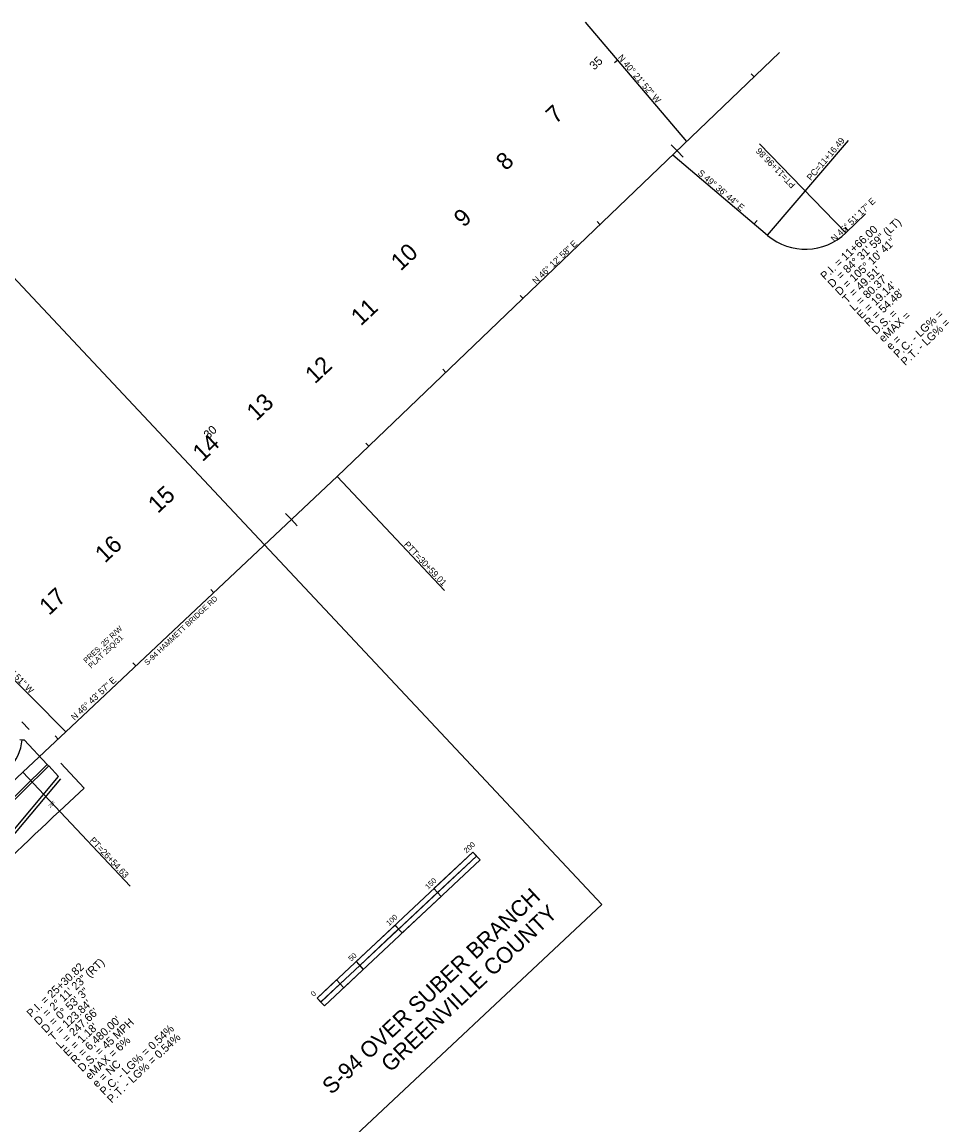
# Model space of a CAD drawing. Extents: x 1623239 to 1625698, y 1118659 to 1120751.
# Drawn here: x 1624829 to 1625698, y 1119717 to 1120751 of the extents above; entities that cross this region are included whole.
import ezdxf

# ---------------------------------------------------------------- set-up
doc = ezdxf.new("R2010")
doc.units = 0
for name, color, linetype in [('RD_EX_DV_TX_Prop', 7, 'Continuous'), ('RD_EX_Road Text', 7, 'Continuous'), ('RD_EX_RW_TX', 7, 'Continuous'), ('RD_HC_Cl', 7, 'Continuous'), ('RD_HC_CL_Rel', 7, 'Continuous'), ('RD_HC_Data', 7, 'Continuous'), ('RD_HC_Data_Tic', 7, 'Continuous'), ('RD_HC_TX_Sta50', 7, 'Continuous'), ('RD_PD_BOC', 7, 'Continuous'), ('RD_PD_CstnLmt', 7, 'Continuous'), ('RD_PD_CstnLmt_TX', 7, 'Continuous'), ('RD_PD_DR_ErosCtrl', 7, 'Continuous'), ('RD_PD_Final_TrvlWay', 7, 'Continuous'), ('RD_PD_PaveShd', 7, 'Continuous'), ('RD_PD_RW', 7, 'Continuous'), ('RD_SHT_ShtClip', 7, 'Continuous'), ('RD_SHT_TX', 7, 'Continuous')]:
    doc.layers.add(name, color=color, linetype=linetype)

msp = doc.modelspace()

# ---------------------------------------------------------------- linework, layer by layer
at = {"layer": 'RD_HC_Cl'}
for p, q in [((1625452.3, 1120638.9), (1625357.3, 1120750.8)), ((1625124.7, 1120324.9), (1625539.1, 1120722.2)), ((1625439.2, 1120626.4), (1625527.9, 1120550.9)), ((1625601.2, 1120553.3), (1625619.5, 1120571.1)), ((1624870.5, 1120085.7), (1625124.7, 1120324.9)), ((1624870.5, 1120085.7), (1624760.8, 1120196.1)), ((1624830.2, 1120047.8), (1624870.5, 1120085.7))]:
    msp.add_line(p, q, dxfattribs=at)
msp.add_arc((1625563.2, 1120592.4), 54.5, 229.6121, 314.1453, dxfattribs=at)
at = {"layer": 'RD_HC_CL_Rel'}
msp.add_arc((1629271.6, 1115329.3), 6480, 133.26746, 135.45725, dxfattribs=at)
at = {"layer": 'RD_HC_Data'}
for p, q in [((1625527.9, 1120550.9), (1625603.6, 1120639.8)), ((1625601.2, 1120553.3), (1625520.4, 1120636.5)), ((1625124.7, 1120324.9), (1625225.2, 1120218.2)), ((1624830.2, 1120047.8), (1624930.7, 1119941))]:
    msp.add_line(p, q, dxfattribs=at)
at = {"layer": 'RD_HC_Data_Tic'}
for p, q in [((1625387.5, 1120715.1), (1625384.5, 1120712.5)), ((1625515.2, 1120699.3), (1625512.5, 1120702.2)), ((1625443, 1120630.1), (1625437.5, 1120635.8)), ((1625448.6, 1120624.3), (1625443, 1120630.1)), ((1625370.8, 1120560.9), (1625368.1, 1120563.8)), ((1625515.4, 1120561.6), (1625518, 1120564.7)), ((1625603.4, 1120555.5), (1625600.6, 1120558.4)), ((1625298.7, 1120491.7), (1625295.9, 1120494.6)), ((1625226.5, 1120422.5), (1625223.7, 1120425.4)), ((1625154.3, 1120353.3), (1625151.5, 1120356.2)), ((1625081.7, 1120284.5), (1625076.2, 1120290.3)), ((1625087.2, 1120278.7), (1625081.7, 1120284.5)), ((1625008.9, 1120215.9), (1625006.1, 1120218.9)), ((1624936.1, 1120147.4), (1624933.3, 1120150.3)), ((1624863.2, 1120078.9), (1624860.5, 1120081.8))]:
    msp.add_line(p, q, dxfattribs=at)
at = {"layer": 'RD_PD_BOC'}
msp.add_line((1624827.4, 1120078.3), (1624829.4, 1120078.2), dxfattribs=at)
at = {"layer": 'RD_PD_CstnLmt'}
for p, q in [((1624863.6, 1120043.8), (1624854.4, 1120053.7)), ((1624814.5, 1119985.2), (1624863.6, 1120043.8))]:
    msp.add_line(p, q, dxfattribs=at)
at = {"layer": 'RD_PD_DR_ErosCtrl'}
msp.add_line((1624816.7, 1119983.1), (1624865.7, 1120041.6), dxfattribs=at)
at = {"layer": 'RD_PD_Final_TrvlWay'}
for p, q in [((1624829.4, 1120078.2), (1624831.4, 1120078)), ((1624831.4, 1120078), (1624853, 1120055.1)), ((1624781.7, 1119985), (1624853, 1120055.1))]:
    msp.add_line(p, q, dxfattribs=at)
msp.add_arc((1624789.5, 1120080.8), 40, 313.3287, 356.1548, dxfattribs=at)
at = {"layer": 'RD_PD_PaveShd'}
for p, q in [((1624783.1, 1119983.5), (1624854.4, 1120053.7)), ((1624853, 1120055.1), (1624854.3, 1120053.7))]:
    msp.add_line(p, q, dxfattribs=at)
at = {"layer": 'RD_PD_RW'}
for p, q in [((1624829.2, 1120094.9), (1624836, 1120087.7)), ((1624865.6, 1120056.3), (1624887.5, 1120033)), ((1624864.5, 1120011.4), (1624887.5, 1120033))]:
    msp.add_line(p, q, dxfattribs=at)
msp.add_arc((1629271.6, 1115329.3), 6430, 133.26746, 135.52479, dxfattribs=at)
at = {"layer": 'RD_SHT_ShtClip'}
for p, q in [((1624620.1, 1120726.2), (1625372.5, 1119923.9)), ((1625372.5, 1119923.9), (1624059.6, 1118692.6))]:
    msp.add_line(p, q, dxfattribs=at)
at = {"layer": 'RD_SHT_TX'}
for p, q in [((1625105.8, 1119836.1), (1625251.7, 1119972.9)), ((1625145.7, 1119866.6), (1625255.1, 1119969.2)), ((1625251.7, 1119972.9), (1625258.5, 1119965.6)), ((1625255.8, 1119968.5), (1625255.8, 1119968.5)), ((1625256.4, 1119967.8), (1625256.4, 1119967.8)), ((1625257.1, 1119967), (1625257.1, 1119967)), ((1625112.7, 1119828.8), (1625258.5, 1119965.6)), ((1625257.8, 1119966.3), (1625257.8, 1119966.3)), ((1625215.2, 1119938.7), (1625222, 1119931.4)), ((1625222, 1119931.4), (1625222, 1119931.4)), ((1625178.7, 1119904.5), (1625185.6, 1119897.2)), ((1625109.2, 1119832.5), (1625145.7, 1119866.6)), ((1625142.3, 1119870.3), (1625149.1, 1119863)), ((1625124, 1119853.2), (1625130.9, 1119845.9)), ((1625149.1, 1119863), (1625149.1, 1119863)), ((1625105.8, 1119836.1), (1625112.7, 1119828.8))]:
    msp.add_line(p, q, dxfattribs=at)
for points in [[(1625215.2, 1119938.7), (1625251.7, 1119972.9), (1625255.1, 1119969.2), (1625218.6, 1119935)], [(1625182.2, 1119900.8), (1625218.6, 1119935), (1625222, 1119931.4), (1625185.6, 1119897.2)], [(1625142.3, 1119870.3), (1625178.8, 1119904.5), (1625182.2, 1119900.9), (1625145.7, 1119866.6)], [(1625127.5, 1119849.6), (1625145.7, 1119866.6), (1625149.1, 1119863), (1625130.9, 1119845.9)], [(1625105.8, 1119836.1), (1625124, 1119853.2), (1625127.5, 1119849.5), (1625109.3, 1119832.4)]]:
    msp.add_lwpolyline(points, close=True, dxfattribs=at)

# ---------------------------------------------------------------- texts
at = {"layer": 'RD_EX_DV_TX_Prop'}
for s, p in [('7', (1625329.3, 1120654.6)), ('8', (1625282.6, 1120610.8)), ('9', (1625243.1, 1120557.7)), ('10', (1625184.1, 1120516.9)), ('11', (1625146.7, 1120465.4)), ('12', (1625103.8, 1120411.1)), ('13', (1625049, 1120376.3)), ('14', (1624998.4, 1120338.1)), ('15', (1624956.6, 1120289.7)), ('16', (1624907, 1120243.2)), ('17', (1624854.7, 1120194.1))]:
    msp.add_text(s, height=16, rotation=43.1627, dxfattribs=at).set_placement(p)
at = {"layer": 'RD_EX_Road Text'}
msp.add_text('S-94 HAMMETT BRIDGE RD', height=5, rotation=43.1627, dxfattribs=at).set_placement((1624946.7, 1120147.7))
at = {"layer": 'RD_EX_RW_TX'}
for s, p in [("PRES. 25' R/W", (1624889.6, 1120149.6)), ('PLAT 25Q/31', (1624894.2, 1120144.7))]:
    msp.add_text(s, height=5, rotation=43.2538, dxfattribs=at).set_placement(p)
at = {"layer": 'RD_HC_Data'}
for s, height, rotation, p in [('N 40%%d 21\' 52" W', 6, 310.3644, (1625387.1, 1120717.2)), ('PC=11+16.49', 6, 49.6121, (1625568.5, 1120601.7)), ('PT=11+96.86', 6, 134.1453, (1625554.5, 1120598.6)), ('S 49%%d 36\' 44" E', 6, 319.6121, (1625461.9, 1120608.4)), ('N 45%%d 51\' 17" E', 6, 44.1453, (1625590.5, 1120544.4)), ('    = 84%%d 31\' 59" (LT)', 7.5, 43.1627, (1625588.4, 1120501.3)), ('P.I. = 11+66.00', 7.5, 43.1627, (1625581.6, 1120508.6)), ('N 46%%d 12\' 58" E', 6, 43.7838, (1625310.9, 1120504.8)), ('D = 105%%d 10\' 41"', 7.5, 43.1627, (1625595.3, 1120494)), ("T = 49.51'", 7.5, 43.1627, (1625602.1, 1120486.7)), ("L = 80.37'", 7.5, 43.1627, (1625609, 1120479.4)), ('D', 7.5, 43.1627, (1625588.4, 1120501.3)), ("E = 19.14'", 7.5, 43.1627, (1625615.8, 1120472.1)), ("R = 54.48'", 7.5, 43.1627, (1625622.6, 1120464.8)), ('D.S. = ', 7.5, 43.1627, (1625629.5, 1120457.5)), ('eMAX = ', 7.5, 43.1627, (1625636.3, 1120450.2)), ('P.C. - LG% = ', 7.5, 43.1627, (1625650, 1120435.6)), ('P.T. - LG% = ', 7.5, 43.1627, (1625656.9, 1120428.3)), ('e = ', 7.5, 43.1627, (1625643.2, 1120442.9)), ('PTT=30+59.01', 6, 313.2675, (1625186.7, 1120260.7)), ('N 44%%d 47\' 51" W', 6, 314.7975, (1624796.9, 1120161.2)), ('N 46%%d 43\' 57" E', 6, 43.2675, (1624878.6, 1120096)), ('PT=26+54.63', 6, 313.2675, (1624892.3, 1119983.5)), ('P.I. = 25+30.82', 7.5, 43.1627, (1624838, 1119817.5)), ('    = 2%%d 11\' 23" (RT)', 7.5, 43.1627, (1624844.9, 1119810.2)), ('D = 0%%d 53\' 3"', 7.5, 43.1627, (1624851.7, 1119802.9)), ("T = 123.84'", 7.5, 43.1627, (1624858.6, 1119795.6)), ("L = 247.66'", 7.5, 43.1627, (1624865.4, 1119788.3)), ('D', 7.5, 43.1627, (1624844.9, 1119810.2)), ("E = 1.18'", 7.5, 43.1627, (1624872.2, 1119781)), ("R = 6,480.00'", 7.5, 43.1627, (1624879.1, 1119773.8)), ('D.S. = 45 MPH', 7.5, 43.1627, (1624885.9, 1119766.5)), ('P.C. - LG% = 0.54%', 7.5, 43.1627, (1624906.4, 1119744.6)), ('P.T. - LG% = 0.54%', 7.5, 43.1627, (1624913.3, 1119737.3)), ('eMAX = 6%', 7.5, 43.1627, (1624892.8, 1119759.2)), ('e = NC', 7.5, 43.1627, (1624899.6, 1119751.9))]:
    msp.add_text(s, height=height, rotation=rotation, dxfattribs=at).set_placement(p)
at = {"layer": 'RD_HC_TX_Sta50'}
for s, p in [('35', (1625365.4, 1120705.3)), ('30', (1625003.9, 1120359.6))]:
    msp.add_text(s, height=8, rotation=42.9276, dxfattribs=at).set_placement(p)
at = {"layer": 'RD_PD_CstnLmt_TX'}
msp.add_text('29F', height=3, rotation=43.3084, dxfattribs=at).set_placement((1624855.6, 1120014.1))
at = {"layer": 'RD_SHT_TX'}
for s, height, rotation, p in [('200', 5, 43.1619, (1625245.9, 1119971.6)), ('150', 5, 43.1587, (1625209.8, 1119937.7)), ('S-94 OVER SUBER BRANCH', 15, 43.1627, (1625119.3, 1119745.1)), ('GREENVILLE COUNTY', 15, 43.1627, (1625174.4, 1119765.9)), ('100', 5, 43.16, (1625173.3, 1119903.5)), ('50', 5, 43.1627, (1625137.8, 1119870.2)), ('0', 5, 43.1592, (1625102.6, 1119837.2))]:
    msp.add_text(s, height=height, rotation=rotation, dxfattribs=at).set_placement(p)

doc.saveas('drawing.dxf')
